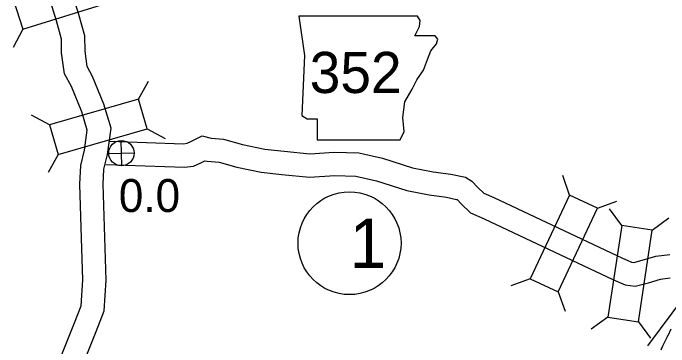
# Model space of a CAD drawing. Extents: x -939622 to -934245, y 1383184 to 1385301.
# Drawn here: x -936194.88 to -936169.66, y 1384666.12 to 1384678.97 of the extents above; entities that cross this region are included whole.
import ezdxf

# ---------------------------------------------------------------- set-up
doc = ezdxf.new("R2010")
doc.units = 0
for name, color, linetype in [('Level 10', 7, 'Continuous'), ('Level 20', 7, 'Continuous'), ('Level 21', 7, 'Continuous'), ('Level 25', 7, 'Continuous'), ('Level 26', 7, 'Continuous'), ('Level 27', 7, 'Continuous')]:
    doc.layers.add(name, color=color, linetype=linetype)

msp = doc.modelspace()

# ---------------------------------------------------------------- linework, layer by layer
at = {"layer": 'Level 10'}
msp.add_line((-936169.579, 1384666.798), (-936169.705, 1384666.547), dxfattribs=at)
for points in [[(-936193.564, 1384661.445), (-936193.515, 1384661.87), (-936193.411, 1384662.384), (-936193.395, 1384662.464), (-936193.087, 1384663.21), (-936191.68, 1384666.711), (-936191.374, 1384667.507), (-936191.299, 1384668.687), (-936191.355, 1384670.337), (-936191.413, 1384672.378), (-936191.385, 1384672.966), (-936191.247, 1384673.523), (-936191.114, 1384674.534), (-936191.385, 1384675.465), (-936191.827, 1384676.535), (-936192.038, 1384676.92), (-936192.114, 1384677.51), (-936192.127, 1384678.09), (-936192.349, 1384678.92), (-936192.865, 1384680.59)], [(-936194.477, 1384661.38), (-936194.405, 1384662.011), (-936194.339, 1384662.335), (-936194.26, 1384662.727), (-936193.921, 1384663.549), (-936192.518, 1384667.04), (-936192.264, 1384667.701), (-936192.2, 1384668.7), (-936192.255, 1384670.309), (-936192.314, 1384672.386), (-936192.28, 1384673.098), (-936192.132, 1384673.69), (-936192.031, 1384674.464), (-936192.235, 1384675.166), (-936192.64, 1384676.146), (-936192.908, 1384676.637), (-936193.013, 1384677.442), (-936193.024, 1384677.961), (-936193.214, 1384678.67), (-936193.73, 1384680.342)], [(-936191.168, 1384674.039), (-936188.329, 1384673.942), (-936188.187, 1384673.96), (-936188.044, 1384674.022), (-936187.605, 1384674.241), (-936187.268, 1384674.155), (-936186.795, 1384674.116), (-936186.062, 1384673.912), (-936185.203, 1384673.736), (-936184.45, 1384673.654), (-936183.465, 1384673.551), (-936182.529, 1384673.618), (-936181.585, 1384673.585), (-936180.669, 1384673.382), (-936179.517, 1384673.016), (-936178.729, 1384672.865), (-936178.049, 1384672.771), (-936177.488, 1384672.648), (-936177.241, 1384672.501), (-936177.011, 1384672.259), (-936176.782, 1384672.041), (-936176.396, 1384671.872), (-936171.449, 1384669.538), (-936171.261, 1384669.457), (-936171.093, 1384669.386), (-936171.005, 1384669.373), (-936170.684, 1384669.455), (-936170.165, 1384669.608), (-936169.623, 1384669.681)], [(-936191.311, 1384673.143), (-936188.288, 1384673.04), (-936187.946, 1384673.083), (-936187.663, 1384673.207), (-936187.504, 1384673.286), (-936187.418, 1384673.264), (-936186.954, 1384673.226), (-936186.274, 1384673.036), (-936185.342, 1384672.846), (-936184.545, 1384672.759), (-936183.48, 1384672.648), (-936182.513, 1384672.717), (-936181.699, 1384672.689), (-936180.903, 1384672.512), (-936179.739, 1384672.142), (-936178.875, 1384671.977), (-936178.208, 1384671.885), (-936177.822, 1384671.8), (-936177.808, 1384671.791), (-936177.648, 1384671.623), (-936177.287, 1384671.28), (-936176.769, 1384671.053), (-936171.819, 1384668.717), (-936171.614, 1384668.629), (-936171.339, 1384668.513), (-936170.958, 1384668.455), (-936170.445, 1384668.587), (-936169.977, 1384668.725), (-936169.617, 1384668.773)], [(-936169.711, 1384666.534), (-936169.881, 1384666.198), (-936169.904, 1384666.146)]]:
    msp.add_lwpolyline(points, dxfattribs=at)
for centre, radius, start, end in [((-936176.382, 1384669.897), 7.47, 333.2451, 333.3596), ((-936162.293, 1384662.664), 8.37, 155.4185, 156.5493)]:
    msp.add_arc(centre, radius, start, end, dxfattribs=at)
at = {"layer": 'Level 20'}
for p, q in [((-936194.509, 1384678.35), (-936194.88, 1384677.65)), ((-936190.055, 1384675.66), (-936189.673, 1384676.354)), ((-936193.476, 1384674.664), (-936194.171, 1384675.045)), ((-936189.722, 1384674.519), (-936189.028, 1384674.138)), ((-936193.144, 1384673.523), (-936193.526, 1384672.829)), ((-936173.476, 1384671.967), (-936173.743, 1384672.712)), ((-936172.401, 1384671.46), (-936171.656, 1384671.727)), ((-936171.473, 1384670.791), (-936171.943, 1384671.429)), ((-936170.299, 1384670.613), (-936169.661, 1384671.082)), ((-936174.997, 1384668.744), (-936175.742, 1384668.476)), ((-936173.922, 1384668.237), (-936173.655, 1384667.491)), ((-936172.009, 1384667.268), (-936172.647, 1384666.798)), ((-936170.834, 1384667.089), (-936170.365, 1384666.451))]:
    msp.add_line(p, q, dxfattribs=at)
for points in [[(-936191.454, 1384680.536), (-936194.86, 1384679.485), (-936194.509, 1384678.35), (-936191.104, 1384679.4)], [(-936190.055, 1384675.66), (-936193.476, 1384674.664), (-936193.144, 1384673.523), (-936189.722, 1384674.519)], [(-936173.476, 1384671.967), (-936174.997, 1384668.744), (-936173.922, 1384668.237), (-936172.401, 1384671.46)], [(-936170.834, 1384667.089), (-936170.299, 1384670.613), (-936171.473, 1384670.791), (-936172.009, 1384667.268)]]:
    msp.add_lwpolyline(points, close=True, dxfattribs=at)
at = {"layer": 'Level 21'}
msp.add_lwpolyline([(-936183.897, 1384678.857), (-936183.668, 1384677.334), (-936183.77, 1384675.025), (-936183.567, 1384674.898), (-936183.186, 1384674.898), (-936183.186, 1384674.086), (-936179.989, 1384674.086), (-936179.836, 1384674.416), (-936179.887, 1384674.949), (-936179.811, 1384675.558), (-936179.532, 1384676.04), (-936179.354, 1384676.395), (-936179.1, 1384676.776), (-936178.948, 1384677.182), (-936178.821, 1384677.512), (-936178.593, 1384677.791), (-936178.542, 1384677.968), (-936178.644, 1384678.095), (-936179.43, 1384678.095), (-936179.253, 1384678.451), (-936179.227, 1384678.679), (-936179.333, 1384678.854)], close=True, dxfattribs=at)
at = {"layer": 'Level 25'}
msp.add_line((-936170.47, 1384666.156), (-936168.6, 1384668.688), dxfattribs=at)
at = {"layer": 'Level 26'}
for p, q in [((-936190.702, 1384673.09), (-936190.725, 1384674.067)), ((-936191.202, 1384673.567), (-936190.225, 1384673.59))]:
    msp.add_line(p, q, dxfattribs=at)
msp.add_circle((-936190.714, 1384673.579), 0.488, dxfattribs=at)
at = {"layer": 'Level 27'}
msp.add_circle((-936181.942, 1384670.111), 1.98, dxfattribs=at)

# ---------------------------------------------------------------- texts
at = {"layer": 'Level 21'}
msp.add_text('352', height=1.584, dxfattribs=at).set_placement((-936183.473, 1384675.893))
at = {"layer": 'Level 25'}
msp.add_text('0.0', height=1.2672, dxfattribs=at).set_placement((-936190.814, 1384671.313))
at = {"layer": 'Level 27'}
msp.add_text('1', height=1.901, dxfattribs=at).set_placement((-936181.942, 1384669.161))

doc.saveas('drawing.dxf')
